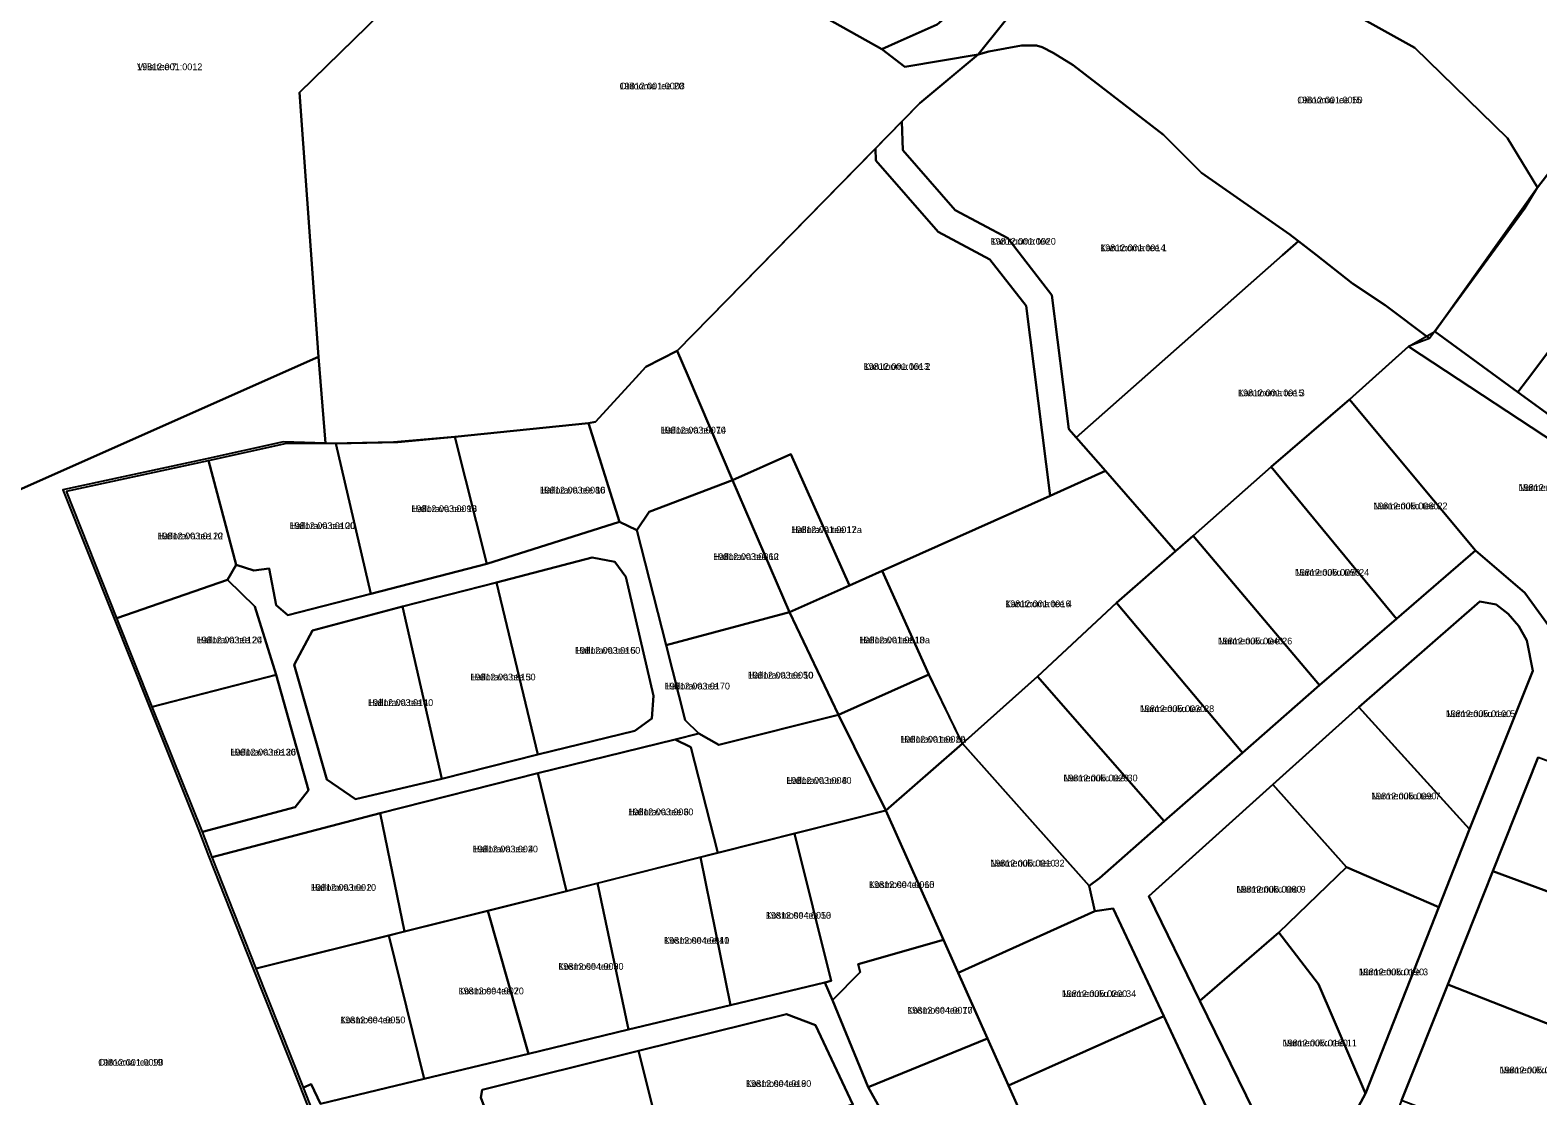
# Model space of a CAD drawing. Extents: x 516875 to 535633, y 6574491 to 6593094.
# Drawn here: x 517287.6 to 517622.6, y 6585495.2 to 6585731.9 of the extents above; entities that cross this region are included whole.
import ezdxf

# ---------------------------------------------------------------- set-up
doc = ezdxf.new("R2010")
doc.units = 0
for name, color, linetype in [('L_AADRESS', 7, 'Continuous'), ('PIIR', 7, 'Continuous'), ('TUNNUS', 7, 'Continuous')]:
    doc.layers.add(name, color=color, linetype=linetype)

msp = doc.modelspace()

# ---------------------------------------------------------------- linework, layer by layer
at = {"layer": 'PIIR'}
for points in [[(517425.89, 6585794.68), (517347.45, 6585718.1), (517351.7, 6585659.34), (517216.44, 6585599.27), (517207.46, 6585595.16), (517196.86, 6585660.95), (517268.42, 6585735.35), (517269.82, 6585736.64), (517310.97, 6585774.8), (517306.23, 6585799.52), (517346.92, 6585840.27), (517349.24, 6585842.6), (517354.45, 6585840.07), (517357.74, 6585841.04), (517361.32, 6585840.14), (517362.66, 6585838.53), (517363.49, 6585826.87), (517364.07, 6585822.12), (517367.97, 6585825.03), (517376.72, 6585831.55), (517414.33, 6585803.36), (517418.19, 6585800.46), (517421.09, 6585798.28)], [(517476.88, 6585727.7), (517480.52, 6585729.32), (517489.18, 6585733.17), (517504.7, 6585746.37), (517508.67, 6585750.47), (517511.04, 6585751.42), (517534.13, 6585778.68), (517549.51, 6585796.47), (517567.47, 6585815.01), (517571.84, 6585809.25), (517568.99, 6585809.08), (517550.63, 6585790.35), (517531.54, 6585767.91), (517503.67, 6585733.28), (517498.26, 6585726.56), (517481.98, 6585723.78)], [(517595.23, 6585786), (517641.72, 6585738.11), (517649.29, 6585731.55), (517632.88, 6585710.34), (517622.55, 6585697), (517615.89, 6585707.97), (517595.29, 6585728.03), (517561.83, 6585746.65)], [(517464.61, 6585734.64), (517457.93, 6585736.11), (517455.93, 6585738.6), (517455.47, 6585741.5), (517446.17, 6585751.31), (517450.47, 6585753.33), (517489.49, 6585772.02), (517504.7, 6585746.37), (517489.18, 6585733.17), (517480.52, 6585729.32), (517476.88, 6585727.7)], [(517539.44, 6585708.71), (517519.42, 6585724.18), (517514.96, 6585726.89), (517512.51, 6585728.18), (517511.23, 6585728.52), (517507.91, 6585728.5), (517500.66, 6585727.17), (517498.26, 6585726.56), (517503.67, 6585733.28), (517531.54, 6585767.91), (517546.96, 6585755.63), (517561.83, 6585746.65), (517595.29, 6585728.03), (517615.89, 6585707.97), (517622.55, 6585697), (517601.84, 6585667.85), (517598.59, 6585663.44), (517588.69, 6585670.81), (517581.43, 6585675.63), (517573.4, 6585681.99), (517567.56, 6585686.53), (517547.91, 6585700.21)], [(517481.34, 6585711.62), (517485.33, 6585715.7), (517490.63, 6585720.16), (517498.26, 6585726.56), (517500.66, 6585727.17), (517507.91, 6585728.5), (517511.23, 6585728.52), (517512.51, 6585728.18), (517514.96, 6585726.89), (517519.42, 6585724.18), (517539.44, 6585708.71), (517547.91, 6585700.21), (517567.56, 6585686.53), (517569.44, 6585685.06), (517565.89, 6585681.92), (517520.09, 6585641.41), (517518.44, 6585643.29), (517514.65, 6585673.05), (517504.85, 6585685.7), (517493.19, 6585691.92), (517481.51, 6585705.29)], [(517475.5, 6585705.67), (517481.34, 6585711.62), (517481.51, 6585705.29), (517493.19, 6585691.92), (517504.85, 6585685.7), (517514.65, 6585673.05), (517518.44, 6585643.29), (517520.09, 6585641.41), (517526.56, 6585634), (517514.28, 6585628.5), (517508.91, 6585670.67), (517500.89, 6585681.01), (517489.4, 6585687.15), (517475.57, 6585702.97)], [(517601.84, 6585667.85), (517619.86, 6585692.46), (517622.55, 6585697), (517632.88, 6585710.34), (517649.46, 6585693.05), (517620.31, 6585654.35), (517618.18, 6585651.53), (517599.73, 6585664.96)], [(517431.4, 6585660.66), (517475.5, 6585705.67), (517475.57, 6585702.97), (517489.4, 6585687.15), (517500.89, 6585681.01), (517508.91, 6585670.67), (517514.28, 6585628.5), (517476.98, 6585611.82), (517469.72, 6585608.57), (517456.67, 6585637.76), (517443.72, 6585631.97), (517433.75, 6585655.21)], [(517620.31, 6585654.35), (517649.46, 6585693.05), (517666.89, 6585678.25), (517638.03, 6585641.46), (517635.85, 6585638.67), (517618.18, 6585651.53)], [(517520.09, 6585641.41), (517565.89, 6585681.92), (517569.44, 6585685.06), (517573.4, 6585681.99), (517581.43, 6585675.63), (517588.69, 6585670.81), (517598.59, 6585663.44), (517595.63, 6585662.31), (517593.91, 6585661.66), (517580.76, 6585649.9), (517563.37, 6585634.93), (517546.07, 6585619.6), (517542.12, 6585616.15), (517526.56, 6585634)], [(517580.76, 6585649.9), (517593.91, 6585661.66), (517632.17, 6585636.47), (517636.9, 6585632.61), (517639.03, 6585629.57), (517626.56, 6585597.49), (517619.77, 6585606.94), (517608.77, 6585616.33)], [(517353.23, 6585640.14), (517343.94, 6585640.44), (517326.53, 6585636.6), (517294.91, 6585629.81), (517306.14, 6585601.62), (517313.96, 6585581.91), (517325.11, 6585554.1), (517327.26, 6585548.48), (517337.06, 6585523.73), (517347.54, 6585497.29), (517351.73, 6585486.7), (517361.88, 6585461.11), (517372.08, 6585435.37), (517389.06, 6585394.42), (517361.73, 6585392.23), (517337.78, 6585390.43), (517305.11, 6585387.97), (517271.21, 6585468.82), (517216.44, 6585599.27), (517351.7, 6585659.34)], [(517413.28, 6585644.95), (517422.18, 6585654.72), (517424.43, 6585657.11), (517431.4, 6585660.66), (517433.75, 6585655.21), (517443.72, 6585631.97), (517425.18, 6585624.91), (517422.43, 6585620.88), (517418.58, 6585622.7), (517411.69, 6585644.65)], [(517580.76, 6585649.9), (517608.77, 6585616.33), (517591.24, 6585601.15), (517563.37, 6585634.93)], [(517411.69, 6585644.65), (517418.58, 6585622.7), (517389.1, 6585613.34), (517381.99, 6585641.57)], [(517355.53, 6585640.12), (517369.29, 6585640.42), (517381.99, 6585641.57), (517389.1, 6585613.34), (517363.31, 6585606.71)], [(517342.26, 6585604.21), (517340.74, 6585612.36), (517337.33, 6585611.92), (517333.39, 6585613.13), (517327.27, 6585636.3), (517344.68, 6585640.14), (517355.53, 6585640.12), (517363.31, 6585606.71), (517344.86, 6585601.93)], [(517443.72, 6585631.97), (517456.67, 6585637.76), (517469.72, 6585608.57), (517456.39, 6585602.61)], [(517295.67, 6585629.49), (517327.27, 6585636.3), (517333.39, 6585613.13), (517331.48, 6585609.79), (517306.9, 6585601.32)], [(517476.98, 6585611.82), (517514.28, 6585628.5), (517526.56, 6585634), (517542.12, 6585616.15), (517528.99, 6585604.7), (517511.47, 6585588.3), (517494.77, 6585573.45), (517487.3, 6585588.77)], [(517563.37, 6585634.93), (517591.24, 6585601.15), (517574.13, 6585586.42), (517546.07, 6585619.6)], [(517422.43, 6585620.88), (517425.18, 6585624.91), (517443.72, 6585631.97), (517456.39, 6585602.61), (517428.92, 6585595.33)], [(517325.89, 6585553.82), (517346.51, 6585559.27), (517349.51, 6585563.04), (517342.28, 6585588.67), (517337.52, 6585603.89), (517331.48, 6585609.79), (517333.39, 6585613.13), (517337.33, 6585611.92), (517340.74, 6585612.36), (517342.26, 6585604.21), (517344.86, 6585601.93), (517363.31, 6585606.71), (517389.1, 6585613.34), (517418.58, 6585622.7), (517422.43, 6585620.88), (517428.92, 6585595.33), (517433.17, 6585578.62), (517436.24, 6585575.64), (517430.93, 6585574.32), (517400.42, 6585566.86), (517365.41, 6585557.96), (517328.04, 6585548.19)], [(517546.07, 6585619.6), (517574.13, 6585586.42), (517556.98, 6585571.36), (517528.99, 6585604.7)], [(517370.38, 6585603.88), (517350.4, 6585598.53), (517346.29, 6585590.89), (517353.55, 6585565.45), (517359.91, 6585561.11), (517379.08, 6585565.58), (517400.47, 6585570.98), (517421.96, 6585576.25), (517425.79, 6585578.99), (517426.13, 6585584.07), (517419.96, 6585610.47), (517417.52, 6585613.84), (517412.51, 6585614.77), (517391.24, 6585609.22)], [(517391.24, 6585609.22), (517412.51, 6585614.77), (517417.52, 6585613.84), (517419.96, 6585610.47), (517426.13, 6585584.07), (517425.79, 6585578.99), (517421.96, 6585576.25), (517400.47, 6585570.98)], [(517456.39, 6585602.61), (517469.72, 6585608.57), (517476.98, 6585611.82), (517487.3, 6585588.77), (517467.22, 6585579.79)], [(517306.9, 6585601.32), (517331.48, 6585609.79), (517337.52, 6585603.89), (517342.28, 6585588.67), (517314.73, 6585581.61)], [(517370.38, 6585603.88), (517391.24, 6585609.22), (517400.47, 6585570.98), (517379.08, 6585565.58)], [(517379.08, 6585565.58), (517359.91, 6585561.11), (517353.55, 6585565.45), (517346.29, 6585590.89), (517350.4, 6585598.53), (517370.38, 6585603.88)], [(517528.99, 6585604.7), (517556.98, 6585571.36), (517539.64, 6585556.2), (517511.47, 6585588.3)], [(517563.74, 6585564.32), (517536.18, 6585539.54), (517547.54, 6585516.3), (517564.67, 6585481.34), (517578.43, 6585488.11), (517580.74, 6585488.97), (517584.33, 6585495.68), (517600.64, 6585537.05), (517607.47, 6585554.38), (517621.56, 6585589.6), (517620.23, 6585596.34), (517618.4, 6585599.51), (517616.02, 6585602.28), (517613.35, 6585604.31), (517609.72, 6585605), (517582.83, 6585581.51)], [(517609.72, 6585605), (517613.35, 6585604.31), (517616.02, 6585602.28), (517618.4, 6585599.51), (517620.23, 6585596.34), (517621.56, 6585589.6), (517607.47, 6585554.38), (517582.83, 6585581.51)], [(517436.24, 6585575.64), (517433.17, 6585578.62), (517428.92, 6585595.33), (517456.39, 6585602.61), (517467.22, 6585579.79), (517440.65, 6585573.12)], [(517314.73, 6585581.61), (517342.28, 6585588.67), (517349.51, 6585563.04), (517346.51, 6585559.27), (517325.89, 6585553.82)], [(517467.22, 6585579.79), (517487.3, 6585588.77), (517494.69, 6585573.39), (517477.73, 6585558.52)], [(517511.47, 6585588.3), (517539.64, 6585556.2), (517525.27, 6585543.5), (517522.95, 6585541.85), (517494.77, 6585573.45)], [(517563.74, 6585564.32), (517582.83, 6585581.51), (517607.47, 6585554.38), (517600.64, 6585537.05), (517580.15, 6585545.95)], [(517434.4, 6585572.6), (517430.93, 6585574.32), (517436.24, 6585575.64), (517440.65, 6585573.12), (517467.22, 6585579.79), (517477.73, 6585558.52), (517440.44, 6585549.16)], [(517400.42, 6585566.86), (517430.93, 6585574.32), (517434.4, 6585572.6), (517440.44, 6585549.16), (517406.8, 6585540.67)], [(517490.57, 6585529.81), (517477.73, 6585558.52), (517494.77, 6585573.45), (517522.95, 6585541.85), (517524.23, 6585536.18), (517493.84, 6585522.5)], [(517622.74, 6585570.44), (517655.93, 6585558.06), (517646.04, 6585532.69), (517612.61, 6585545.06)], [(517365.41, 6585557.96), (517400.42, 6585566.86), (517406.8, 6585540.67), (517370.8, 6585531.65)], [(517580.15, 6585545.95), (517565.08, 6585531.46), (517547.54, 6585516.3), (517536.18, 6585539.54), (517563.74, 6585564.32)], [(517365.41, 6585557.96), (517370.8, 6585531.65), (517337.85, 6585523.46), (517328.04, 6585548.19)], [(517472.04, 6585522.65), (517465.93, 6585516.45), (517464.19, 6585520.35), (517465.61, 6585520.7), (517457.5, 6585553.44), (517477.73, 6585558.52), (517490.57, 6585529.81), (517471.63, 6585524.43)], [(517436.56, 6585548.18), (517440.44, 6585549.16), (517457.5, 6585553.44), (517465.61, 6585520.7), (517464.19, 6585520.35), (517443.25, 6585515.32)], [(517413.69, 6585542.4), (517436.56, 6585548.18), (517443.25, 6585515.32), (517420.61, 6585509.87)], [(517573.92, 6585520), (517565.08, 6585531.46), (517580.15, 6585545.95), (517600.64, 6585537.05), (517584.33, 6585495.68)], [(517612.61, 6585545.06), (517646.04, 6585532.69), (517645.31, 6585530.49), (517636.05, 6585506.82), (517602.61, 6585519.89)], [(517389.35, 6585536.29), (517406.8, 6585540.67), (517413.69, 6585542.4), (517420.61, 6585509.87), (517398.36, 6585504.52)], [(517367.29, 6585530.78), (517370.8, 6585531.65), (517389.35, 6585536.29), (517398.36, 6585504.52), (517375.15, 6585498.93)], [(517500.36, 6585507.91), (517493.84, 6585522.5), (517524.23, 6585536.18), (517528.27, 6585536.78), (517539.5, 6585512.87), (517505.05, 6585497.44)], [(517375.15, 6585498.93), (517352.14, 6585493.4), (517350.08, 6585497.78), (517348.34, 6585497.03), (517337.85, 6585523.46), (517367.29, 6585530.78)], [(517547.54, 6585516.3), (517565.08, 6585531.46), (517573.92, 6585520), (517584.33, 6585495.68), (517580.74, 6585488.97), (517578.43, 6585488.11), (517564.67, 6585481.34)], [(517465.93, 6585516.45), (517472.04, 6585522.65), (517471.63, 6585524.43), (517490.57, 6585529.81), (517500.36, 6585507.91), (517473.83, 6585497.06)], [(517602.61, 6585519.89), (517636.05, 6585506.82), (517633.44, 6585499.85), (517630.09, 6585483.27), (517628.2, 6585480.41), (517592.35, 6585494.1)], [(517388.06, 6585496.5), (517387.76, 6585494.77), (517395.45, 6585474.04), (517406.82, 6585444.29), (517438.21, 6585458.67), (517479.83, 6585470.94), (517470.42, 6585493.22), (517462.16, 6585510.88), (517455.72, 6585513.27), (517422.79, 6585505.16)], [(517428.85, 6585481.01), (517422.79, 6585505.16), (517455.72, 6585513.27), (517462.16, 6585510.88), (517470.42, 6585493.22), (517431.54, 6585481.56)], [(517511.79, 6585482.36), (517505.05, 6585497.44), (517539.5, 6585512.87), (517551.03, 6585488.24), (517516.16, 6585472.6)], [(517476.7, 6585491.92), (517473.83, 6585497.06), (517500.36, 6585507.91), (517511.79, 6585482.36), (517484.79, 6585471.8)], [(517428.85, 6585481.01), (517395.45, 6585474.04), (517387.76, 6585494.77), (517388.06, 6585496.5), (517422.79, 6585505.16)]]:
    msp.add_lwpolyline(points, close=True, dxfattribs=at)
for points in [[(517464.61, 6585734.64), (517476.88, 6585727.7), (517481.98, 6585723.78), (517498.26, 6585726.56), (517485.33, 6585715.7), (517431.4, 6585660.66), (517424.43, 6585657.11), (517422.18, 6585654.72), (517413.28, 6585644.95), (517411.69, 6585644.65), (517381.99, 6585641.57), (517368.36, 6585640.41), (517354.61, 6585640.11), (517353.23, 6585640.14), (517351.7, 6585659.34), (517347.45, 6585718.1), (517425.89, 6585794.68)], [(517632.17, 6585636.47), (517593.91, 6585661.66), (517599.73, 6585664.96), (517618.18, 6585651.53), (517635.85, 6585638.67)], [(517551.03, 6585488.24), (517539.5, 6585512.87), (517528.27, 6585536.78), (517524.23, 6585536.18), (517522.95, 6585541.85), (517525.27, 6585543.5), (517539.64, 6585556.2), (517556.98, 6585571.36), (517574.13, 6585586.42), (517591.24, 6585601.15), (517608.77, 6585616.33), (517619.77, 6585606.94), (517626.56, 6585597.49)], [(517622.74, 6585570.44), (517612.61, 6585545.06), (517602.61, 6585519.89), (517592.35, 6585494.1), (517582.32, 6585468.5), (517576.45, 6585454.26), (517580.7, 6585441.36), (517583.45, 6585438.22), (517606.27, 6585427.73), (517608.6, 6585429.17), (517612.01, 6585428.24), (517612.91, 6585425.92), (517625.2, 6585422.28)], [(517352.54, 6585486.45), (517348.34, 6585497.03), (517350.08, 6585497.78), (517352.14, 6585493.4), (517375.15, 6585498.93), (517398.36, 6585504.52), (517420.61, 6585509.87), (517443.25, 6585515.32), (517464.19, 6585520.35), (517465.93, 6585516.45), (517473.83, 6585497.06), (517476.7, 6585491.92)]]:
    msp.add_lwpolyline(points, dxfattribs=at)

# ---------------------------------------------------------------- texts
at = {"layer": 'L_AADRESS'}
for s, p in [('Villa tee 7', (517311.38, 6585723.05)), ('Otitooma tee 20', (517418.59, 6585718.79)), ('Otitooma tee 15', (517569.2, 6585715.68)), ('Karutooma tee', (517501.03, 6585684.28)), ('Karutooma tee 1', (517525.39, 6585682.83)), ('Karutooma tee 2', (517472.84, 6585656.46)), ('Karutooma tee 3', (517556.02, 6585650.6)), ('Hallorava tee 14', (517427.7, 6585642.32)), ('Nurmenuku tee 20', (517618.37, 6585629.57)), ('Hallorava tee 16', (517400.88, 6585628.99)), ('Hallorava tee 18', (517372.32, 6585624.86)), ('Nurmenuku tee 22', (517586.07, 6585625.48)), ('Hallorava tee 20', (517345.29, 6585621.09)), ('Hallorava tee 12a', (517456.72, 6585620.2)), ('Hallorava tee 22', (517315.91, 6585618.81)), ('Hallorava tee 12', (517439.41, 6585614.22)), ('Nurmenuku tee 24', (517568.66, 6585610.71)), ('Karutooma tee 4', (517504.28, 6585603.73)), ('Hallorava tee 24', (517324.61, 6585595.7)), ('Hallorava tee 10a', (517471.84, 6585595.69)), ('Hallorava tee 5', (517408.69, 6585593.38)), ('Nurmenuku tee 26', (517551.56, 6585595.46)), ('Hallorava tee 3', (517385.43, 6585587.46)), ('Hallorava tee 10', (517447.1, 6585587.87)), ('Hallorava tee', (517428.62, 6585585.45)), ('Hallorava tee 1', (517362.68, 6585581.79)), ('Nurmenuku tee 28', (517534.22, 6585580.42)), ('Nurmenuku tee 5', (517602.2, 6585579.31)), ('Hallorava tee 8a', (517480.95, 6585573.64)), ('Hallorava tee 26', (517332.12, 6585570.77)), ('Hallorava tee 8', (517455.64, 6585564.48)), ('Nurmenuku tee 30', (517517.21, 6585565.03)), ('Nurmenuku tee 7', (517585.61, 6585561.02)), ('Hallorava tee 6', (517420.5, 6585557.5)), ('Hallorava tee 4', (517385.95, 6585549.25)), ('Nurmenuku tee 32', (517500.98, 6585546.1)), ('Hallorava tee 2', (517349.98, 6585540.71)), ('Kosmose tee 15', (517474.04, 6585541.35)), ('Nurmenuku tee 9', (517555.66, 6585540.31)), ('Kosmose tee 13', (517451.09, 6585534.52)), ('Kosmose tee 11', (517428.47, 6585528.95)), ('Kosmose tee 9', (517404.98, 6585523.16)), ('Nurmenuku tee 3', (517582.86, 6585521.94)), ('Kosmose tee 7', (517382.82, 6585517.72)), ('Nurmenuku tee 34', (517516.88, 6585517.11)), ('Kosmose tee 17', (517482.52, 6585513.43)), ('Kosmose tee 5', (517356.5, 6585511.27)), ('Nurmenuku tee 11', (517565.93, 6585506.16)), ('Otitooma tee 19', (517302.75, 6585501.86)), ('Nurmenuku tee 10', (517614.15, 6585500.15)), ('Kosmose tee 8', (517446.69, 6585497.14))]:
    msp.add_text(s, height=1.5, dxfattribs=at).set_placement(p)
at = {"layer": 'TUNNUS'}
for s, p in [('19812:001:0012', (517311.38, 6585723.05)), ('19812:001:0008', (517418.59, 6585718.79)), ('19812:001:0050', (517569.2, 6585715.68)), ('19812:001:0020', (517501.03, 6585684.28)), ('19812:001:0014', (517525.39, 6585682.83)), ('19812:001:0013', (517472.84, 6585656.46)), ('19812:001:0015', (517556.02, 6585650.6)), ('19812:003:0070', (517427.7, 6585642.32)), ('19812:005:0070', (517618.37, 6585629.57)), ('19812:003:0080', (517400.88, 6585628.99)), ('19812:003:0090', (517372.32, 6585624.86)), ('19812:005:0060', (517586.07, 6585625.48)), ('19812:003:0100', (517345.29, 6585621.09)), ('19812:001:0017', (517456.72, 6585620.2)), ('19812:003:0110', (517315.91, 6585618.81)), ('19812:003:0060', (517439.41, 6585614.22)), ('19812:005:0050', (517568.66, 6585610.71)), ('19812:001:0016', (517504.28, 6585603.73)), ('19812:003:0120', (517324.61, 6585595.7)), ('19812:001:0018', (517471.84, 6585595.69)), ('19812:003:0160', (517408.69, 6585593.38)), ('19812:005:0040', (517551.56, 6585595.46)), ('19812:003:0150', (517385.43, 6585587.46)), ('19812:003:0050', (517447.1, 6585587.87)), ('19812:003:0170', (517428.62, 6585585.45)), ('19812:003:0140', (517362.68, 6585581.79)), ('19812:005:0030', (517534.22, 6585580.42)), ('19812:005:0100', (517602.2, 6585579.31)), ('19812:001:0019', (517480.95, 6585573.64)), ('19812:003:0130', (517332.12, 6585570.77)), ('19812:003:0040', (517455.64, 6585564.48)), ('19812:005:0020', (517517.21, 6585565.03)), ('19812:005:0090', (517585.61, 6585561.02)), ('19812:003:0030', (517420.5, 6585557.5)), ('19812:003:0020', (517385.95, 6585549.25)), ('19812:005:0010', (517500.98, 6585546.1)), ('19812:003:0010', (517349.98, 6585540.71)), ('19812:004:0060', (517474.04, 6585541.35)), ('19812:005:0080', (517555.66, 6585540.31)), ('19812:004:0050', (517451.09, 6585534.52)), ('19812:004:0040', (517428.47, 6585528.95)), ('19812:004:0030', (517404.98, 6585523.16)), ('19812:005:0190', (517582.86, 6585521.94)), ('19812:004:0020', (517382.82, 6585517.72)), ('19812:005:0200', (517516.88, 6585517.11)), ('19812:004:0070', (517482.52, 6585513.43)), ('19812:004:0010', (517356.5, 6585511.27)), ('19812:005:0180', (517565.93, 6585506.16)), ('19812:001:0090', (517302.75, 6585501.86)), ('19812:005:0150', (517614.15, 6585500.15)), ('19812:004:0190', (517446.69, 6585497.14))]:
    msp.add_text(s, height=1.5, dxfattribs=at).set_placement(p)

doc.saveas('drawing.dxf')
